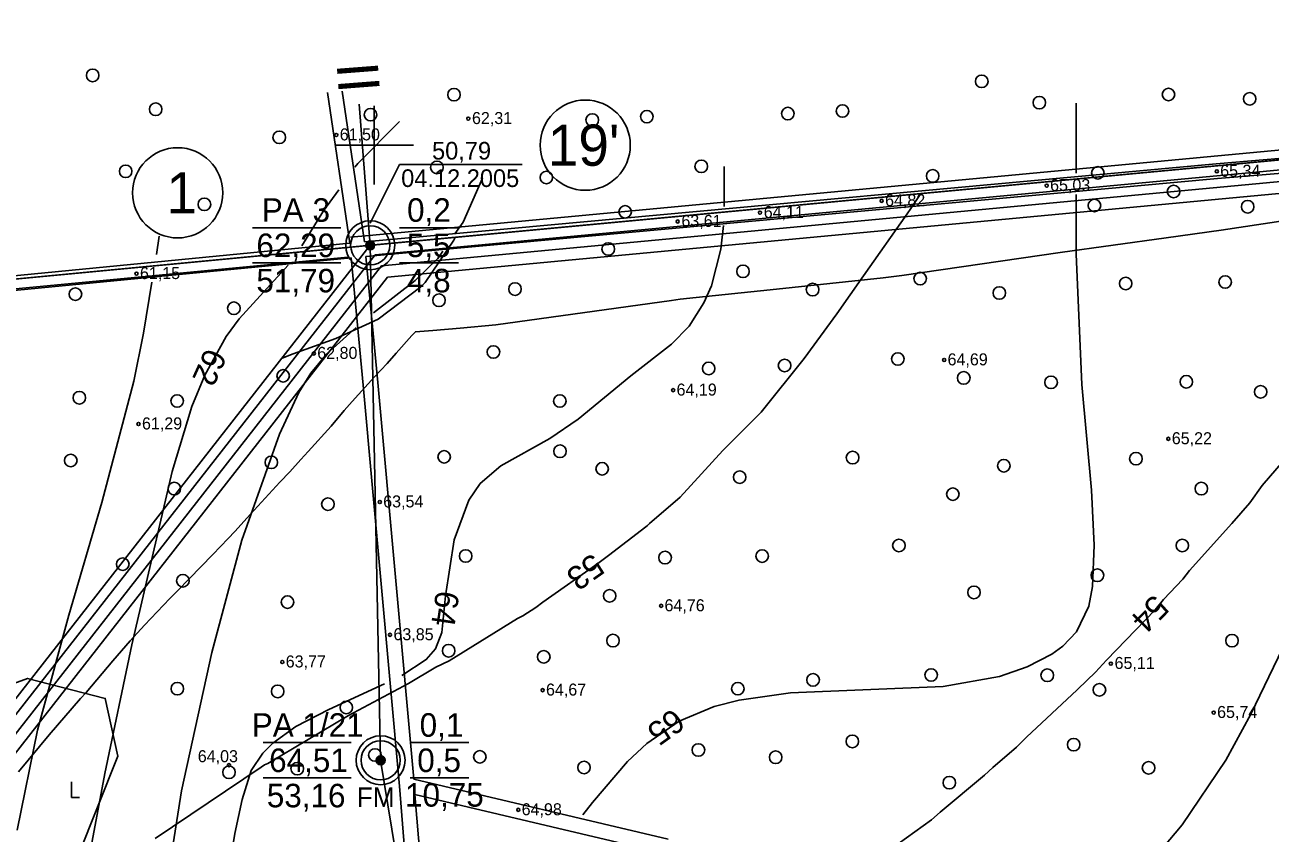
# Model space of a CAD drawing. Extents: x 532503 to 539665, y 6557663 to 6561526.
# Drawn here: x 534128.7 to 534382.9, y 6559859.6 to 6560024.5 of the extents above; entities that cross this region are included whole.
import ezdxf

# ---------------------------------------------------------------- set-up
doc = ezdxf.new("R2010")
doc.units = 0
for name, color, linetype in [('Default', 7, 'Continuous'), ('GEOLPUNKT', 7, 'Continuous'), ('HALJASTUS', 7, 'Continuous'), ('HORISONTAAL-EH2000', 7, 'Continuous'), ('illumineerimisjooned', 7, 'Continuous'), ('kataster', 7, 'Continuous'), ('KORGUS-EH2000', 7, 'Continuous'), ('Lamami horisontaal_EH2000', 7, 'Continuous'), ('Lõige', 7, 'Continuous'), ('PIIR', 7, 'Continuous'), ('PIIR_me', 7, 'Continuous'), ('Plokid', 7, 'Continuous'), ('Proovid', 7, 'Continuous'), ('TEE', 7, 'Continuous'), ('TM_aktiivne', 7, 'Continuous'), ('Veetase', 7, 'Continuous'), ('VORK', 7, 'Continuous')]:
    doc.layers.add(name, color=color, linetype=linetype)

# ---------------------------------------------------------------- blocks, each defined once
blk = doc.blocks.new('RAIESM')
at = {"layer": 'Default'}
for points in [[(0, 2), (0, 0)], [(0, 0), (1, 0)]]:
    blk.add_lwpolyline(points, dxfattribs=at)
blk = doc.blocks.new('METS')
at = {"layer": 'HALJASTUS'}
blk.add_circle((0, 0), 0.8, dxfattribs=at)

msp = doc.modelspace()

# ---------------------------------------------------------------- linework, layer by layer
at = {"layer": 'GEOLPUNKT'}
for p, q in [((534175.17, 6559983.16), (534193.17, 6559983.16)), ((534205.17, 6559983.16), (534217.17, 6559983.16)), ((534175.17, 6559975.96), (534193.17, 6559975.96)), ((534205.17, 6559975.96), (534217.17, 6559975.96)), ((534177.3, 6559878.1), (534195.3, 6559878.1)), ((534207.3, 6559878.1), (534219.3, 6559878.1)), ((534177.3, 6559870.9), (534195.3, 6559870.9)), ((534207.3, 6559870.9), (534219.3, 6559870.9))]:
    msp.add_line(p, q, dxfattribs=at)
for centre, radius in [((534199.17, 6559979.56), 5), ((534199.17, 6559979.56), 4), ((534199.17, 6559979.56), 0.9), ((534199.17, 6559979.56), 0.801), ((534199.17, 6559979.56), 0.7), ((534199.17, 6559979.56), 0.6), ((534199.17, 6559979.56), 0.5), ((534199.17, 6559979.56), 0.4), ((534199.17, 6559979.56), 0.3), ((534199.17, 6559979.56), 0.2), ((534199.17, 6559979.56), 0.1), ((534201.3, 6559874.5), 5), ((534201.3, 6559874.5), 4), ((534201.3, 6559874.5), 0.9), ((534201.3, 6559874.5), 0.801), ((534201.3, 6559874.5), 0.7), ((534201.3, 6559874.5), 0.6), ((534201.3, 6559874.5), 0.5), ((534201.3, 6559874.5), 0.4), ((534201.3, 6559874.5), 0.3), ((534201.3, 6559874.5), 0.2), ((534201.3, 6559874.5), 0.1)]:
    msp.add_circle(centre, radius, dxfattribs=at)
at = {"layer": 'HALJASTUS'}
msp.add_lwpolyline([(534020.23, 6559948.58), (534037.72, 6559925.98), (534054.08, 6559915.24), (534069.41, 6559912.68), (534077.59, 6559900.41), (534080.66, 6559886.09), (534091.4, 6559877.39), (534112.36, 6559885.07), (534129.23, 6559891.2), (534145.08, 6559887.11), (534147.64, 6559875.35), (534139.46, 6559854.89), (534110.31, 6559789.42), (534101.11, 6559757.71), (534086.8, 6559745.95), (534070.44, 6559724.98), (534054.08, 6559721.91), (534040.79, 6559718.84), (534030.56, 6559697.87), (534027.49, 6559680.99), (534017.27, 6559666.67), (534010.62, 6559633.93), (534011.64, 6559613.48)], dxfattribs=at)
at = {"layer": 'HORISONTAAL-EH2000'}
for points in [[(534343.27, 6559994.31), (534343.28, 6560008.58)], [(534205.12, 6560004.79), (534196.62, 6559996.25), (534196.06, 6559995.47)], [(534271.45, 6559995.65), (534271.41, 6559987.48)], [(534216.44, 6559981.9), (534218.11, 6559984.3), (534222.11, 6559993.24)], [(534192.76, 6559990.91), (534189.62, 6559986.57), (534185.18, 6559979.48)], [(534242.56, 6559863.37), (534244.52, 6559865.9), (534251.68, 6559874.27), (534255.66, 6559877.94), (534262.25, 6559882.45), (534269.4, 6559885.44), (534274.47, 6559886.77), (534284.98, 6559888.25), (534316.12, 6559889.57), (534327.62, 6559891.62), (534333.26, 6559893.57), (534338.31, 6559896.16), (534340.57, 6559897.79), (534343.36, 6559900.69), (534345.83, 6559905.95), (534346.62, 6559909.93), (534346.94, 6559918.36), (534346.4, 6559929.61), (534344.44, 6559951.18), (534343.25, 6559977.78), (534343.26, 6559989.95)], [(534271.31, 6559983.57), (534270.77, 6559978.76), (534268.83, 6559971.31), (534267.3, 6559967.8), (534264.25, 6559963.05), (534260.64, 6559959.37), (534252.35, 6559952.94), (534241.59, 6559944.09), (534235.84, 6559940.12), (534225.83, 6559934.55), (534221.63, 6559930.99), (534219.29, 6559927.54), (534216.33, 6559919.47), (534214.55, 6559908.08), (534213.81, 6559900.55), (534212.51, 6559897.27), (534210.62, 6559895.05), (534205.65, 6559891.78)], [(534155.51, 6559977.7), (534156.12, 6559981.44)], [(534199.82, 6559965.77), (534208.35, 6559972.4), (534212.97, 6559976.89), (534213.98, 6559978.35)], [(534182.43, 6559975.49), (534172.44, 6559964.53), (534169.77, 6559960.94), (534165.41, 6559953.1), (534162.77, 6559946.69), (534158.72, 6559933.41), (534150.52, 6559898.08), (534144.99, 6559871.77), (534141.6, 6559853.64), (534138.19, 6559834.34), (534136.21, 6559825.74), (534131.22, 6559808.83), (534126.06, 6559795.09)], [(534127.07, 6559860.24), (534131.23, 6559880.67), (534137.63, 6559904.09), (534144.35, 6559927.06), (534150.94, 6559951.85), (534152.92, 6559961.66), (534154.6, 6559972.04)], [(534139.12, 6559756.96), (534138.5, 6559763.84), (534138.55, 6559772.33), (534138.99, 6559776.54), (534140.7, 6559784.67), (534145.97, 6559800.53), (534152.02, 6559819.79), (534153.85, 6559827.53), (534156.71, 6559843.2), (534160.62, 6559868.3), (534166.83, 6559896.51), (534172.94, 6559919.42), (534180.67, 6559941), (534184.58, 6559949.52), (534187.02, 6559953.46), (534190.29, 6559957.45), (534196.28, 6559962.81)], [(534443.39, 6559949.02), (534436.51, 6559946.74), (534429.24, 6559945.53), (534419.96, 6559943.88), (534415.73, 6559942.3), (534409.93, 6559938.22), (534406.53, 6559934.63), (534400.62, 6559926.35), (534396.08, 6559918.65), (534388.2, 6559903.1), (534378.92, 6559883.92), (534373.8, 6559874.53), (534364.89, 6559861.31), (534360.98, 6559856.64), (534352.36, 6559847.99), (534341.3, 6559839.05), (534340.37, 6559838.42)], [(534202.11, 6559890.1), (534190.75, 6559884.84), (534184, 6559881.37), (534179.28, 6559877.96), (534177.24, 6559875.93), (534174.88, 6559872.43), (534173.01, 6559866.49), (534171.52, 6559859.58), (534170.06, 6559850.36), (534168.2, 6559839.11), (534166.24, 6559830.18), (534163.71, 6559820.26), (534161.06, 6559811.41), (534158.04, 6559801.93), (534155.21, 6559790.54), (534152.89, 6559775.47), (534152.55, 6559762.1)]]:
    msp.add_lwpolyline(points, dxfattribs=at)
at = {"layer": 'illumineerimisjooned'}
for points in [[(534195.15, 6559981.19), (534198.98, 6559981.55), (535160.12, 6560071.77), (535418.53, 6559993.82), (535458.87, 6559929.25), (535494.63, 6559867.7), (535482.6, 6559826), (535251.74, 6559649.68), (535250.36, 6559648.53), (535180.45, 6559687.33), (534941.15, 6559814.59), (534876.93, 6559774.72), (534959.62, 6559531.32), (534733.77, 6559483.15), (534375.91, 6559461.87), (534195.51, 6559444.47)], [(533951.03, 6559666.04), (533951.15, 6559953.97), (534194.63, 6559977.12)]]:
    msp.add_lwpolyline(points, dxfattribs=at)
msp.add_lwpolyline([(534967.67, 6560049.69), (534974.15, 6559828.08), (535058.69, 6559883.05), (535223.5, 6560002.45), (535218.56, 6560049.92), (535415.93, 6559990.42), (535455.45, 6559927.19), (535490.31, 6559867.16), (535479.12, 6559828.38), (535249.57, 6559653.05), (535182.36, 6559690.84), (534940.99, 6559819.22), (534872.14, 6559776.44), (534954.37, 6559534.34), (534950.91, 6559533.67), (534733.22, 6559487.12), (534375.58, 6559465.86), (534199.95, 6559448.92), (533951.79, 6559660.13), (534200.21, 6559977.65), (534931.63, 6560046.31)], close=True, dxfattribs=at)
at = {"layer": 'kataster'}
msp.add_lwpolyline([(535159.89, 6560069.73), (534198.28, 6559979.48), (533949.2, 6559955.8), (533947.7, 6559658.95), (533880.05, 6559759.56), (533755.25, 6559939.22), (533571.3, 6560208.36), (533567.86, 6560213.61), (533625.2, 6560245.66), (533707.68, 6560291.77), (533833.45, 6560362.07), (533959.67, 6560429.27), (534159.72, 6560456.15), (534530.65, 6560498.79), (534889.13, 6560540.24)], dxfattribs=at)
msp.add_lwpolyline([(533947.7, 6559658.95), (533949.2, 6559955.8), (534198.28, 6559979.48), (535159.89, 6560069.73), (535417.31, 6559992.13), (535457.22, 6559928.24), (535504.86, 6559846.09), (535250.3, 6559650.84), (535181.52, 6559689.04), (534941.15, 6559817.08), (534874.65, 6559775.26), (534957.01, 6559532.73), (534735.22, 6559485.45), (534375.71, 6559463.85), (534199.28, 6559446.9), (534122.84, 6559439.44), (534110.45, 6559447.36), (534092.53, 6559453.94), (534085.13, 6559454.75)], close=True, dxfattribs=at)
at = {"layer": 'KORGUS-EH2000'}
for centre in [(534219.18, 6560005.4), (534192.25, 6560002.07), (534371.98, 6559994.65), (534337.26, 6559991.73), (534303.57, 6559988.64), (534278.73, 6559986.23), (534261.93, 6559984.42), (534151.47, 6559973.78), (534187.66, 6559957.49), (534316.33, 6559956.18), (534261, 6559950), (534151.88, 6559943.1), (534362.09, 6559940.08), (534201.12, 6559927.19), (534258.55, 6559906), (534203.21, 6559900.09), (534181.22, 6559894.54), (534350.34, 6559894.23), (534234.35, 6559888.8), (534371.34, 6559884.23), (534170.33, 6559873.5), (534229.39, 6559864.38)]:
    msp.add_circle(centre, 0.32, dxfattribs=at)
at = {"layer": 'Lamami horisontaal_EH2000'}
for points in [[(534155.29, 6559858.51), (534176.9, 6559873.07), (534177.58, 6559873.55), (534178.28, 6559873.82), (534194.72, 6559883.63), (534206.99, 6559890.16), (534212.53, 6559893.5), (534215.31, 6559894.79), (534229.21, 6559903.44), (534230.34, 6559903.94), (534232.99, 6559905.68), (534234.39, 6559906.74), (534245.64, 6559914.62), (534247.83, 6559916.29), (534255.43, 6559922.15), (534255.76, 6559922.4), (534256.16, 6559922.81), (534262.45, 6559928.21), (534271.17, 6559937.7), (534278.43, 6559944.97), (534278.97, 6559945.55), (534287.78, 6559956.45), (534294.45, 6559965.57), (534299.86, 6559973.32), (534308.78, 6559986), (534309.55, 6559987.06), (534311.53, 6559990.11)], [(534181.18, 6559956.57), (534183.42, 6559957.39), (534192.12, 6559960.52), (534198.3, 6559963.37), (534200.82, 6559964.48), (534209.52, 6559971.08), (534210.41, 6559971.98), (534216.24, 6559980.58), (534216.48, 6559981.18)], [(534305.24, 6559856.21), (534313.72, 6559862.38), (534315.5, 6559863.9), (534324.56, 6559871.47), (534326.28, 6559873.05), (534331.11, 6559877.15), (534333.16, 6559879.21), (534343.46, 6559888.85), (534343.61, 6559889.01), (534347.2, 6559892.48), (534349.44, 6559894.91), (534359.42, 6559905.19), (534361.1, 6559907.31), (534365.02, 6559911.48), (534366.42, 6559913.24), (534375.05, 6559922.81), (534378.73, 6559927.01), (534381.24, 6559930.58), (534386.79, 6559937.02)]]:
    msp.add_lwpolyline(points, dxfattribs=at)
at = {"layer": 'Lõige'}
msp.add_lwpolyline([(534196.94, 6560008.33), (534199.17, 6559979.56), (534201.3, 6559874.5), (534215.74, 6559786.31), (534234.02, 6559626.35), (534236.27, 6559544.42), (534237.9, 6559498.78), (534199.31, 6559446.85), (534164.07, 6559400.22), (534154.58, 6559387.66)], dxfattribs=at)
at = {"layer": 'PIIR'}
for centre, radius in [((534243.06, 6559999.99), 9.2), ((534159.87, 6559990.27), 9.2), ((534199.17, 6559979.56), 0.88), ((534199.17, 6559979.56), 0.88), ((534199.17, 6559979.56), 0.88)]:
    msp.add_circle(centre, radius, dxfattribs=at)
at = {"layer": 'PIIR_me'}
for points in [[(534199.17, 6559979.56), (534441.63, 6560002.32), (534688.17, 6560025.46)], [(534733.49, 6559485.13), (534485.11, 6559470.37), (534375.74, 6559463.87), (534199.3, 6559446.85), (533949.03, 6559659.85), (534199.17, 6559979.56)]]:
    msp.add_lwpolyline(points, dxfattribs=at)
at = {"layer": 'Plokid'}
for points in [[(534951.24, 6559536.08), (534732.91, 6559489.51), (534375.41, 6559468.25), (534200.75, 6559451.41), (533955.1, 6559660.46), (534201.47, 6559975.36), (534969.74, 6560047.47)], [(534950.46, 6559538.37), (534732.58, 6559491.9), (534375.22, 6559470.64), (534201.53, 6559453.89), (533958.41, 6559660.8), (534202.72, 6559973.06), (534969.81, 6560045.07)], [(534127.34, 6559872.11), (534133.6, 6559879.69), (534140.06, 6559887.11), (534141.18, 6559888.35), (534146.65, 6559894.8), (534150.19, 6559898.86), (534153.12, 6559902.04), (534158.24, 6559907.49), (534159.9, 6559909.17), (534166.96, 6559916.4), (534168.69, 6559918.21), (534170.09, 6559919.65), (534171.58, 6559921.26), (534173.98, 6559923.9), (534180.73, 6559931.23), (534182.73, 6559933.37), (534185, 6559935.84), (534186.47, 6559937.5), (534191.19, 6559942.67), (534193.86, 6559945.88), (534195.47, 6559947.71), (534200.01, 6559952.72), (534202.61, 6559955.45), (534204.47, 6559957.54), (534207.68, 6559961.13), (534208.39, 6559961.92), (534211.98, 6559962.18), (534217.54, 6559962.65), (534224.82, 6559963.32), (534260.66, 6559968.27), (534262.42, 6559968.56), (534265.73, 6559968.9), (534280.83, 6559970.47), (534285.29, 6559970.98), (534303.89, 6559972.9), (534307.68, 6559973.39), (534340, 6559978.06), (534361.63, 6559981.1), (534372.87, 6559982.65), (534402.18, 6559987.09)]]:
    msp.add_lwpolyline(points, dxfattribs=at)
at = {"layer": 'TEE'}
for p, q in [((534193.44, 6560010.99), (534197.98, 6559980.28)), ((534190.45, 6560010.73), (534194.99, 6559980)), ((534440.43, 6560002.01), (534371.84, 6559996.15)), ((534440.67, 6559999.02), (534372.11, 6559993.16)), ((534371.84, 6559996.15), (534227.93, 6559982.96)), ((534372.11, 6559993.16), (534228.17, 6559979.97)), ((534227.93, 6559982.96), (534197.98, 6559980.28)), ((534194.99, 6559980), (534085.29, 6559969.37)), ((534228.17, 6559979.97), (534198.26, 6559977.3)), ((534195.27, 6559977.02), (534085.29, 6559966.37)), ((534197.74, 6559951.02), (534195.27, 6559977.02)), ((534200.69, 6559951.56), (534198.26, 6559977.3)), ((534205.15, 6559869.25), (534197.74, 6559951.02)), ((534200.69, 6559951.56), (534208.04, 6559870.64)), ((534214.08, 6559759.73), (534205.15, 6559869.25)), ((534208.04, 6559870.64), (534259.99, 6559858.44)), ((534217.07, 6559760.02), (534208.3, 6559867.51)), ((534208.3, 6559867.51), (534259.33, 6559855.51))]:
    msp.add_line(p, q, dxfattribs=at)
at = {"layer": 'TM_aktiivne'}
msp.add_lwpolyline([(535159.92, 6560069.74), (535417.23, 6559992.12), (535457.16, 6559928.22), (535492.47, 6559867.43), (535480.86, 6559827.19), (535250.49, 6559651.24), (535250.13, 6559650.94), (535181.4, 6559689.09), (534941.07, 6559816.9), (534874.53, 6559775.58), (534957, 6559532.81), (534733.5, 6559485.14), (534375.75, 6559463.86), (534199.32, 6559446.85), (534124.95, 6559439.68), (533949.03, 6559659.85), (533949.15, 6559955.79), (534199.17, 6559979.56)], close=True, dxfattribs=at)
at = {"layer": 'Veetase'}
for p, q in [((534199.17, 6559984.06), (534205.17, 6559996.06)), ((534205.17, 6559996.06), (534230.17, 6559996.06))]:
    msp.add_line(p, q, dxfattribs=at)
at = {"layer": 'VORK'}
for p, q in [((534200, 6560008), (534200, 6559992)), ((534192, 6560000), (534208, 6560000))]:
    msp.add_line(p, q, dxfattribs=at)

# ---------------------------------------------------------------- block references
at = {"layer": 'HALJASTUS', "xscale": 1.6, "yscale": 1.6000000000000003}
for name, p in [('METS', (534142.5, 6560014.22)), ('METS', (534324, 6560013.01)), ('METS', (534216.26, 6560010.29)), ('METS', (534362.12, 6560010.32)), ('METS', (534155.38, 6560007.32)), ('METS', (534295.57, 6560006.96)), ('METS', (534335.76, 6560008.67)), ('METS', (534378.69, 6560009.44)), ('METS', (534199.22, 6560006.21)), ('METS', (534244.49, 6560005.13)), ('METS', (534255.64, 6560005.81)), ('METS', (534284.41, 6560006.43)), ('METS', (534180.6, 6560001.58)), ('METS', (534149.25, 6559994.66)), ('METS', (534212.78, 6559995.45)), ('METS', (534266.74, 6559995.67)), ('METS', (534347.69, 6559994.35)), ('METS', (534235.12, 6559993.39)), ('METS', (534313.98, 6559993.72)), ('METS', (534363.16, 6559990.53)), ('METS', (534165.32, 6559987.91)), ('METS', (534347, 6559987.69)), ('METS', (534378.29, 6559987.43)), ('METS', (534251.22, 6559986.38)), ('METS', (534247.76, 6559978.8)), ('METS', (534275.26, 6559974.24)), ('METS', (534311.43, 6559972.77)), ('METS', (534353.38, 6559971.78)), ('METS', (534373.69, 6559972.07)), ('METS', (534138.99, 6559969.6)), ('METS', (534228.73, 6559970.63)), ('METS', (534289.47, 6559970.53)), ('METS', (534327.6, 6559969.84)), ('METS', (534171.34, 6559966.72)), ('METS', (534213.22, 6559968.35)), ('METS', (534224.32, 6559957.8)), ('METS', (534306.87, 6559956.37)), ('METS', (534268.26, 6559954.44)), ('METS', (534283.75, 6559955.04)), ('METS', (534181.41, 6559952.93)), ('METS', (534320.32, 6559952.51)), ('METS', (534338.15, 6559951.6)), ('METS', (534365.75, 6559951.72)), ('METS', (534380.93, 6559949.67)), ('METS', (534139.8, 6559948.46)), ('METS', (534159.76, 6559947.81)), ('METS', (534237.88, 6559947.79)), ('METS', (534214.26, 6559936.4)), ('METS', (534237.91, 6559937.55)), ('METS', (534297.63, 6559936.25)), ('METS', (534355.47, 6559936.03)), ('METS', (534138.04, 6559935.66)), ('METS', (534178.99, 6559935.28)), ('METS', (534246.51, 6559933.97)), ('METS', (534328.5, 6559934.59)), ('METS', (534274.59, 6559932.26)), ('METS', (534159.18, 6559929.93)), ('METS', (534318.1, 6559928.79)), ('METS', (534368.81, 6559929.93)), ('METS', (534190.53, 6559926.75)), ('METS', (534307.09, 6559918.32)), ('METS', (534364.93, 6559918.32)), ('METS', (534218.64, 6559916.17)), ('METS', (534259.36, 6559915.85)), ('METS', (534279.17, 6559916.16)), ('METS', (534148.65, 6559914.5)), ('METS', (534160.93, 6559911.13)), ('METS', (534347.61, 6559912.25)), ('METS', (534248.04, 6559908.06)), ('METS', (534322.41, 6559908.75)), ('METS', (534182.28, 6559906.77)), ('METS', (534248.72, 6559898.92)), ('METS', (534375.07, 6559898.91)), ('METS', (534215.17, 6559896.85)), ('METS', (534234.59, 6559895.6)), ('METS', (534289.57, 6559890.9)), ('METS', (534313.67, 6559891.91)), ('METS', (534337.37, 6559891.85)), ('METS', (534159.79, 6559889.1)), ('METS', (534180.28, 6559888.55)), ('METS', (534274.21, 6559889.1)), ('METS', (534348.02, 6559888.88)), ('METS', (534194.29, 6559885.28)), ('METS', (534297.59, 6559878.35)), ('METS', (534342.77, 6559877.69)), ('METS', (534200.13, 6559875.57)), ('METS', (534221.54, 6559875.21)), ('METS', (534266.16, 6559876.6)), ('METS', (534281.92, 6559875.12)), ('METS', (534184.27, 6559872.79)), ('METS', (534242.81, 6559873.03)), ('METS', (534358.05, 6559872.97)), ('METS', (534170.33, 6559872.06)), ('METS', (534317.39, 6559869.93)), ('RAIESM', (534138.22, 6559866.89))]:
    msp.add_blockref(name, p, dxfattribs=at)

# ---------------------------------------------------------------- texts
at = {"layer": 'GEOLPUNKT'}
for s, p in [('PA 3', (534177.05, 6559984.36)), ('0,2', (534206.69, 6559984.36)), ('62,29', (534175.93, 6559977.16)), ('5,5', (534206.64, 6559977.16)), ('51,79', (534175.93, 6559969.96)), ('4,8', (534206.66, 6559969.96)), ('PA 1/21', (534174.99, 6559879.3)), ('0,1', (534209.26, 6559879.3)), ('64,51', (534178.53, 6559872.1)), ('0,5', (534208.77, 6559872.1)), ('53,16', (534178.06, 6559864.9)), ('10,75', (534206.28, 6559865.04))]:
    msp.add_text(s, height=4.8, dxfattribs=at).set_placement(p)
at = {"layer": 'HORISONTAAL-EH2000'}
for s, rotation, p in [('62', 245.7005, (534165.68, 6559958.9)), ('64', 261.5064, (534212.65, 6559909.3)), ('65', 215.7507, (534261.07, 6559885.3))]:
    msp.add_text(s, height=4.8, rotation=rotation, dxfattribs=at).set_placement(p)
at = {"layer": 'KORGUS-EH2000'}
for s, p in [('62,31', (534219.94, 6560004.3)), ('61,50', (534192.95, 6560000.97)), ('65,34', (534372.67, 6559993.55)), ('65,03', (534337.95, 6559990.63)), ('64,82', (534304.27, 6559987.54)), ('63,61', (534262.69, 6559983.32)), ('64,11', (534279.5, 6559985.13)), ('61,15', (534152.17, 6559972.67)), ('62,80', (534188.36, 6559956.39)), ('64,69', (534317.02, 6559955.07)), ('64,19', (534261.7, 6559948.9)), ('61,29', (534152.58, 6559942)), ('65,22', (534362.79, 6559938.98)), ('63,54', (534201.82, 6559926.09)), ('64,76', (534259.24, 6559904.9)), ('63,85', (534203.91, 6559898.99)), ('63,77', (534181.92, 6559893.44)), ('65,11', (534351.11, 6559893.13)), ('64,67', (534235.05, 6559887.7)), ('65,74', (534372.04, 6559883.13)), ('64,03', (534163.97, 6559874.11)), ('64,98', (534230.08, 6559863.28))]:
    msp.add_text(s, height=2.45, dxfattribs=at).set_placement(p)
at = {"layer": 'Lamami horisontaal_EH2000'}
for s, rotation, p in [('53', 215.4185, (534244.63, 6559916.92)), ('54', 225.4018, (534359.17, 6559908.57))]:
    msp.add_text(s, height=4.8, rotation=rotation, dxfattribs=at).set_placement(p)
at = {"layer": 'Lõige'}
msp.add_text('II', height=8.4, rotation=274.431, dxfattribs=at).set_placement((534192.3, 6560016.61))
at = {"layer": 'PIIR'}
for s, p in [("19'", (534235.4, 6559995.79)), ('1', (534157.55, 6559986.07))]:
    msp.add_text(s, height=8.4, dxfattribs=at).set_placement(p)
at = {"layer": 'Proovid'}
msp.add_text('FM', height=4, dxfattribs=at).set_placement((534196.42, 6559864.96))
at = {"layer": 'Veetase'}
for s, p in [('50,79', (534211.79, 6559997.06)), ('04.12.2005', (534205.49, 6559991.46))]:
    msp.add_text(s, height=3.6, dxfattribs=at).set_placement(p)

doc.saveas('drawing.dxf')
